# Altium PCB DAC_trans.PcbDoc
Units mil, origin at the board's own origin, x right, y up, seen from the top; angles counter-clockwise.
Board outline 825 x 2320 mil, 2 copper layers (Top Layer, Bottom Layer); 2 components, 36 nets, 80 pads, 0 vias.
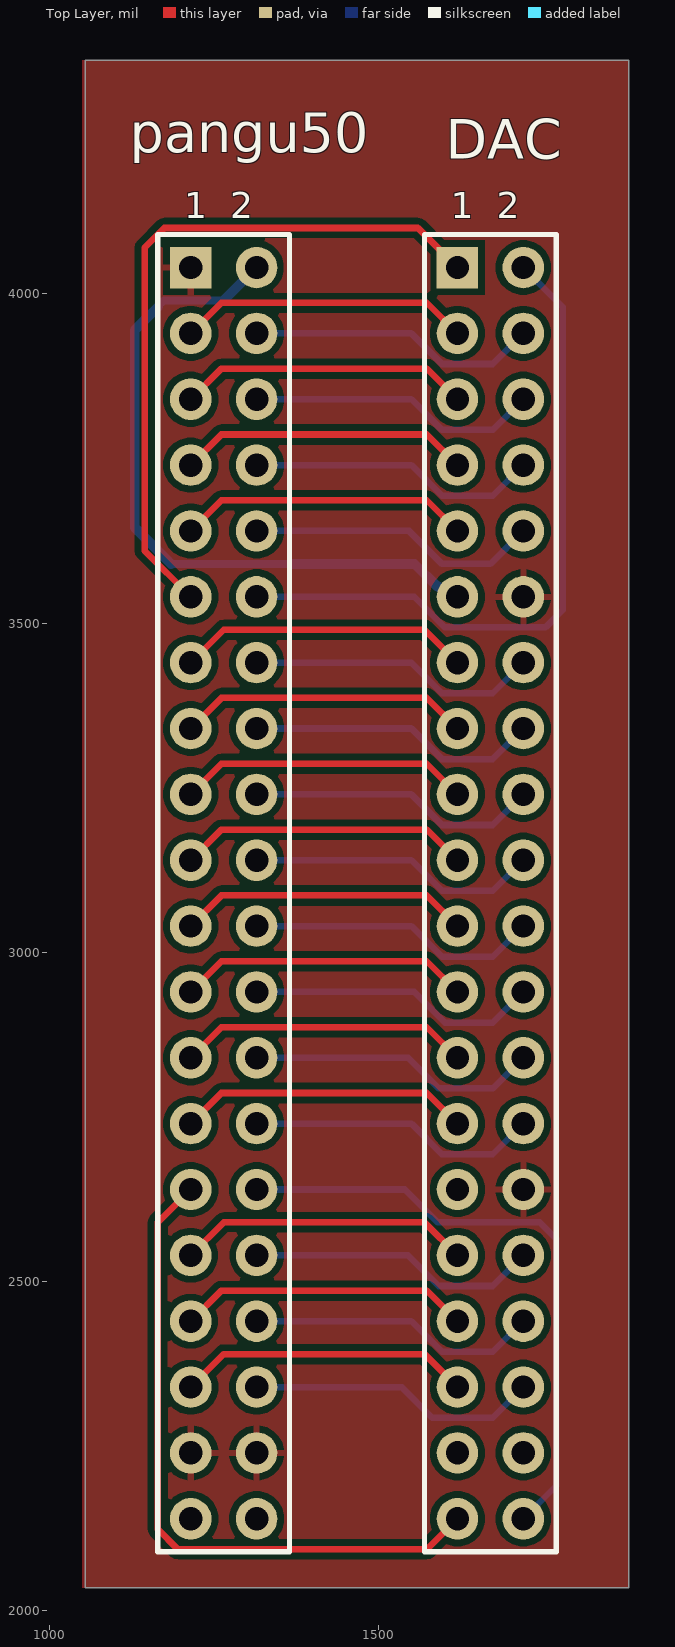
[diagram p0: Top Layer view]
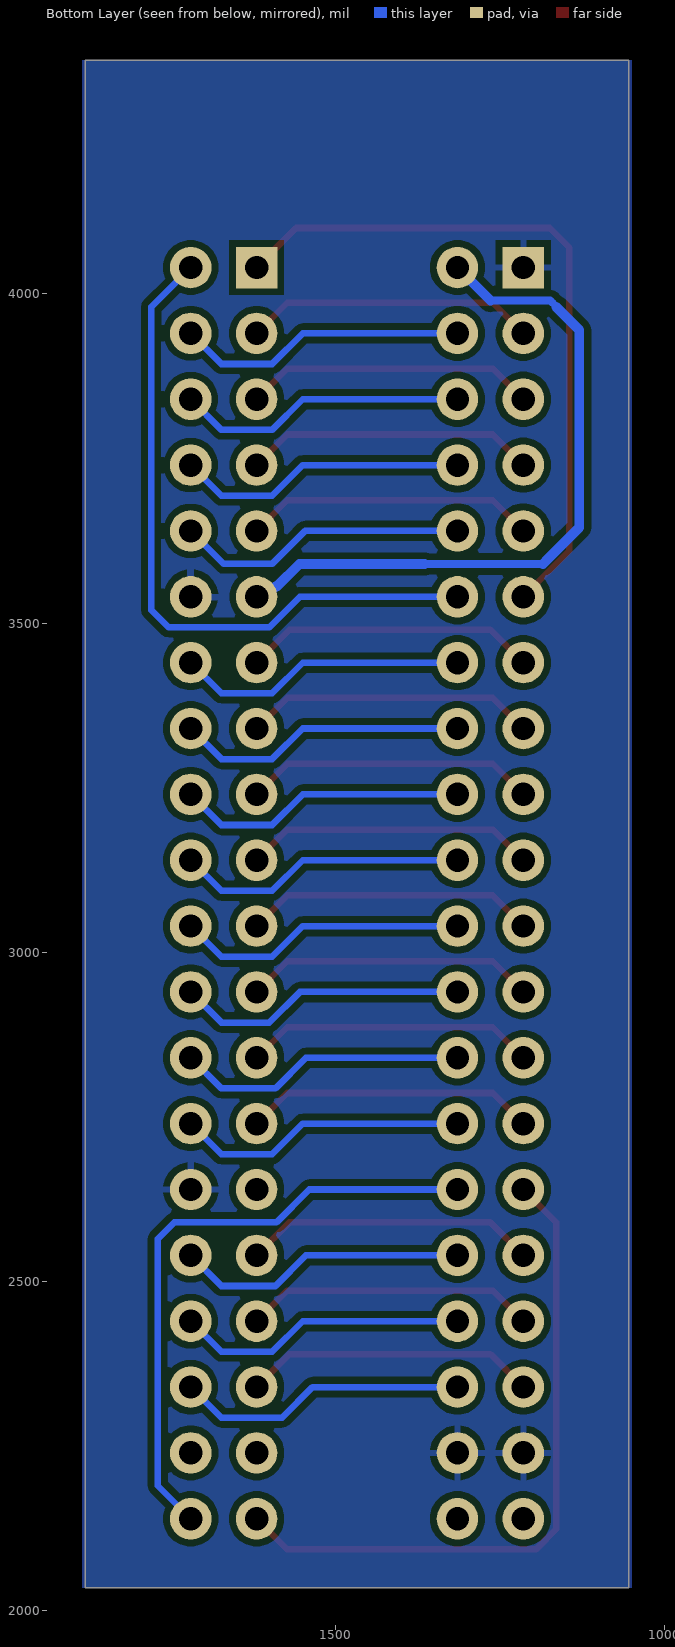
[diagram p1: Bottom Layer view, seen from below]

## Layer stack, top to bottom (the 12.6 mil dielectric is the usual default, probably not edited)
Top Solder: solder mask 0.4, Solder Resist, Dk 3.5
Top Layer: signal copper 1.4
Dielectric 1: dielectric 12.6, FR-4, Dk 4.8
Bottom Layer: signal copper 1.4
Bottom Solder: solder mask 0.4, Solder Resist, Dk 3.5

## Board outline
1055,2035 1055,4355 1880,4355 1880,2035

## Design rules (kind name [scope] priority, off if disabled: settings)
Clearance [All] p1: gap=10 ignorepadtopadclearanceinfootprint=FALSE except(0: Arc-Hole Track-Hole SMDPad-Hole THPad-Hole Via-Hole Fill-Hole Poly-Hole Region-Hole Text-Hole)
PolygonConnect [All] p1: connectstyle=Relief reliefconductorwidth=10 reliefentries=4 polygonreliefangle="90 Angle" airgapwidth=10
RoutingVias [All] p1: holewidth=28 width=50 viastyle="Through Hole" minholewidth=28 minwidth=50 maxholewidth=28 maxwidth=50
SolderMaskExpansion [All] p1: expansion=4 istentingtop=FALSE
Width [All] p1: maxlimit=20 minlimit=10 preferedwidth=10
30 further rules are at their usual default settings.

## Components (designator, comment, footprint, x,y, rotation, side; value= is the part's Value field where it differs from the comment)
DAC "Header 2X20" "Header 2.54 2X20P" 1620,4040 r270 top
pangu50 "Header 2X20" "Header 2.54 2X20P" 1215,4040 r270 top

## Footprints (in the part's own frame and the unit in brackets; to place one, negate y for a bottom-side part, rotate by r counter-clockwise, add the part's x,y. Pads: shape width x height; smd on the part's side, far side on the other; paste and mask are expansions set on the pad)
"Header 2.54 2X20P" [mm]
  rect 1.6x1.6 hole 0.9: 1(0,0)
  round 1.6 hole 0.9: 2(0,2.54) 3(2.54,0) 4(2.54,2.54) 5(5.08,0) 6(5.08,2.54) 7(7.62,0) 8(7.62,2.54) 9(10.16,0) 10(10.16,2.54) 11(12.7,0) 12(12.7,2.54) 13(15.24,0) 14(15.24,2.54) 15(17.78,0) 16(17.78,2.54) 17(20.32,0) 18(20.32,2.54) 19(22.86,0) 20(22.86,2.54) 21(25.4,0) 22(25.4,2.54) 23(27.94,0) 24(27.94,2.54) 25(30.48,0) 26(30.48,2.54) 27(33.02,0) 28(33.02,2.54) 29(35.56,0) 30(35.56,2.54) 31(38.1,0) 32(38.1,2.54) 33(40.64,0) 34(40.64,2.54) 35(43.18,0) 36(43.18,2.54) 37(45.72,0) 38(45.72,2.54) 39(48.26,0) 40(48.26,2.54)
  silkscreen extent -1.27,-1.27 49.53,3.81

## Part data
DAC pangu50: library part "Header 20X2", "20*2P接插件"

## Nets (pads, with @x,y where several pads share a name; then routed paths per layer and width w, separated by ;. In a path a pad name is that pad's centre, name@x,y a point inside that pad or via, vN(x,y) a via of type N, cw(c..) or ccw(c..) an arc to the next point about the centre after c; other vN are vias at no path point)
EX_IO_1N: DAC.35 pangu50.35 | length 446.4
  Top Layer w10: pangu50.35 1265,2390 1570,2390 DAC.35
EX_IO_1P: DAC.36 pangu50.36 | length 443.5
  Bottom Layer w10: pangu50.36 1535,2340 1581.5,2293.5 1673.5,2293.5 DAC.36
EX_IO_2N: DAC.33 pangu50.33 | length 443.5
  Top Layer w10: pangu50.33 1261.5,2486.5 1573.5,2486.5 DAC.33
EX_IO_2P: DAC.34 pangu50.34 | length 443.5
  Bottom Layer w10: pangu50.34 1550,2440 1596.5,2393.5 1673.5,2393.5 DAC.34
EX_IO_3N: DAC.25 pangu50.25 | length 443.5
  Top Layer w10: pangu50.25 1261.5,2886.5 1573.5,2886.5 DAC.25
EX_IO_3P: DAC.26 pangu50.26 | length 443.5
  Bottom Layer w10: pangu50.26 1545,2840 1591.5,2793.5 1673.5,2793.5 DAC.26
EX_IO_4N: DAC.27 pangu50.27 | length 443.5
  Top Layer w10: pangu50.27 1261.5,2786.5 1573.5,2786.5 DAC.27
EX_IO_4P: DAC.28 pangu50.28 | length 443.5
  Bottom Layer w10: pangu50.28 1550,2740 1596.5,2693.5 1673.5,2693.5 DAC.28
EX_IO_5N: DAC.31 pangu50.31 | length 446.4
  Top Layer w10: pangu50.31 1265,2590 1570,2590 DAC.31
EX_IO_5P: DAC.32 pangu50.32 | length 443.5
  Bottom Layer w10: pangu50.32 1545,2540 1591.5,2493.5 1673.5,2493.5 DAC.32
EX_IO_6N: DAC.39 pangu50.29 | length 1023.5
  Top Layer w10: pangu50.29 1165,2590 1165,2124.24 1195.74,2093.5 1573.5,2093.5 DAC.39
EX_IO_6P: DAC.40 pangu50.30 | length 931.8
  Bottom Layer w10: pangu50.30 1540,2640 1590,2590 1745,2590 1770,2565 1770,2190 DAC.40
EX_IO_7N: DAC.15 pangu50.15 | length 443.5
  Top Layer w10: pangu50.15 1261.5,3386.5 1573.5,3386.5 DAC.15
EX_IO_7P: DAC.16 pangu50.16 | length 443.5
  Bottom Layer w10: pangu50.16 1550,3340 1596.5,3293.5 1673.5,3293.5 DAC.16
EX_IO_8N: DAC.17 pangu50.17 | length 443.5
  Top Layer w10: pangu50.17 1261.5,3286.5 1573.28,3286.5 1619.78,3240 DAC.17
EX_IO_8P: DAC.18 pangu50.18 | length 443.5
  Bottom Layer w10: pangu50.18 1550,3240 1596.5,3193.5 1673.5,3193.5 DAC.18
EX_IO_9N: DAC.5 pangu50.5 | length 443.5
  Top Layer w10: pangu50.5 1261.5,3886.5 1573.5,3886.5 DAC.5
EX_IO_9P: DAC.6 pangu50.6 | length 443.5
  Bottom Layer w10: pangu50.6 1550,3840 1596.5,3793.5 1673.5,3793.5 DAC.6
EX_IO_10N: DAC.7 pangu50.7 | length 443.5
  Top Layer w10: pangu50.7 1261.5,3786.5 1573.5,3786.5 DAC.7
EX_IO_10P: DAC.8 pangu50.8 | length 443.5
  Bottom Layer w10: pangu50.8 1550,3740 1596.5,3693.5 1673.5,3693.5 DAC.8
EX_IO_11N: DAC.3 pangu50.3 | length 443.5
  Top Layer w10: pangu50.3 1261.5,3986.5 1573.5,3986.5 DAC.3
EX_IO_11P: DAC.4 pangu50.4 | length 443.5
  Bottom Layer w10: pangu50.4 1550,3940 1596.5,3893.5 1673.5,3893.5 DAC.4
EX_IO_12N: DAC.9 pangu50.9 | length 443.5
  Top Layer w10: pangu50.9 1261.5,3686.5 1573.5,3686.5 DAC.9
EX_IO_12P: DAC.10 pangu50.10 | length 446.4
  Bottom Layer w10: pangu50.10 1546.41,3640 1596.41,3590 1670,3590 DAC.10
EX_IO_13N: DAC.21 pangu50.21 | length 443.5
  Top Layer w10: pangu50.21 1261.5,3086.5 1573.5,3086.5 DAC.21
EX_IO_13P: DAC.22 pangu50.22 | length 443.5
  Bottom Layer w10: pangu50.22 1550,3040 1596.5,2993.5 1673.5,2993.5 DAC.22
EX_IO_14N: DAC.19 pangu50.19 | length 443.5
  Top Layer w10: pangu50.19 1261.5,3186.5 1573.5,3186.5 DAC.19
EX_IO_14P: DAC.20 pangu50.20 | length 443.5
  Bottom Layer w10: pangu50.20 1550,3140 1596.5,3093.5 1673.5,3093.5 DAC.20
EX_IO_15N: DAC.1 pangu50.11 | length 1071.3
  Top Layer w10: pangu50.11 1145,3610 1145,4070 1175,4100 1560,4100 DAC.1
EX_IO_15P: DAC.2 pangu50.12 | length 1040.1
  Bottom Layer w10: pangu50.12 1554.24,3540 1600.74,3493.5 1753.5,3493.5 1780,3520 1780,3980 DAC.2
EX_IO_16N: DAC.13 pangu50.13 | length 446.4
  Top Layer w10: pangu50.13 1265,3490 1570,3490 DAC.13
EX_IO_16P: DAC.14 pangu50.14 | length 443.5
  Bottom Layer w10: pangu50.14 1550,3440 1596.5,3393.5 1673.5,3393.5 DAC.14
EX_IO_17N: DAC.23 pangu50.23 | length 443.5
  Top Layer w10: pangu50.23 1261.5,2986.5 1573.5,2986.5 DAC.23
EX_IO_17P: DAC.24 pangu50.24 | length 443.5
  Bottom Layer w10: pangu50.24 1554.24,2940 1600.74,2893.5 1673.5,2893.5 DAC.24
GND: DAC.12 DAC.30 pangu50.1 pangu50.37 pangu50.38
VCC5: DAC.11 pangu50.2 | length 1058.2
  Bottom Layer w10: 1165,3980 1165,3980.64 1170.86,3986.5
  Bottom Layer w12: 1170.86,3986.5 1174.36,3990 1265,3990 ; 1185,3590 1365,3590
  Bottom Layer w15: 1165,3980 1130,3945 1130,3645 1177.07,3597.93 1185,3590 ; 1265,3990 pangu50.2 ; 1365,3590 1555,3590 1589.32,3555.68 1591.33,3555.68 1607.01,3540 DAC.11
pads on no net: DAC.29 DAC.37 DAC.38 pangu50.39 pangu50.40

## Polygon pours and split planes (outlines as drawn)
GND on Bottom Layer "GND_L02_P000" (solid, pour order 0): 1050,4355 1885,4355 1885,2035 1050,2035
GND on Top Layer "GND_L01_P001" (solid, pour order 1): 1050,4355 1880,4355 1880,2035 1050,2035

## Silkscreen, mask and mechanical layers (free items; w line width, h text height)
Top Overlay:
  text "1  2" at 1205,4115 h40
  text "1  2" at 1610,4115 h40
Mechanical 1:
  lines w10: 1055,2035 1055,4355 1080,4355 1880,4355 1880,2035 1055,2035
